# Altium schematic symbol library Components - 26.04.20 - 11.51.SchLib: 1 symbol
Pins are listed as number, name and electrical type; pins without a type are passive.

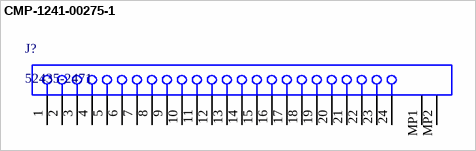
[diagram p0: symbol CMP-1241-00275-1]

## CMP-1241-00275-1
designator J?, comment 52435-2471
0.5 mm Pitch Easy-On(TM) Type FPC Connector, 2.0 mm Mated Height, Right Angle, ZIF, SMT, Top Contact, 24 Circuits, -40 to 85 degC, ELV and RoHS Compliant, Tape and Reel; Manufacturer: Molex; Pitch - Mating Interface: 0.50mm; PCB Locator: No; Current (Max per Contact): 0.5A; PCB Retention: Yes; Circuits (Loaded): 24; Material - Metal: Phosphor Bronze; Material - Plating Termination: Gold; Mated Height: 2.00mm; Entry Angle: 90degrees Angle; Durability (mating cycles max): 20; Voltage (Max): 50V AC (RMS)/DC
footprint MOLX-52435-2471 (FPC Connector, 24-Leads, Right Angle, Pitch 0.5 mm, Mated Height 2.0 mm, SMT)
pins: 1, 2, 3, 4, 5, 6, 7, 8, 9, 10, 11, 12, 13, 14, 15, 16, 17, 18, 19, 20, 21, 22, 23, 24, MP1, MP2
